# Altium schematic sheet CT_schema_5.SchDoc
size 297 x 173 mm
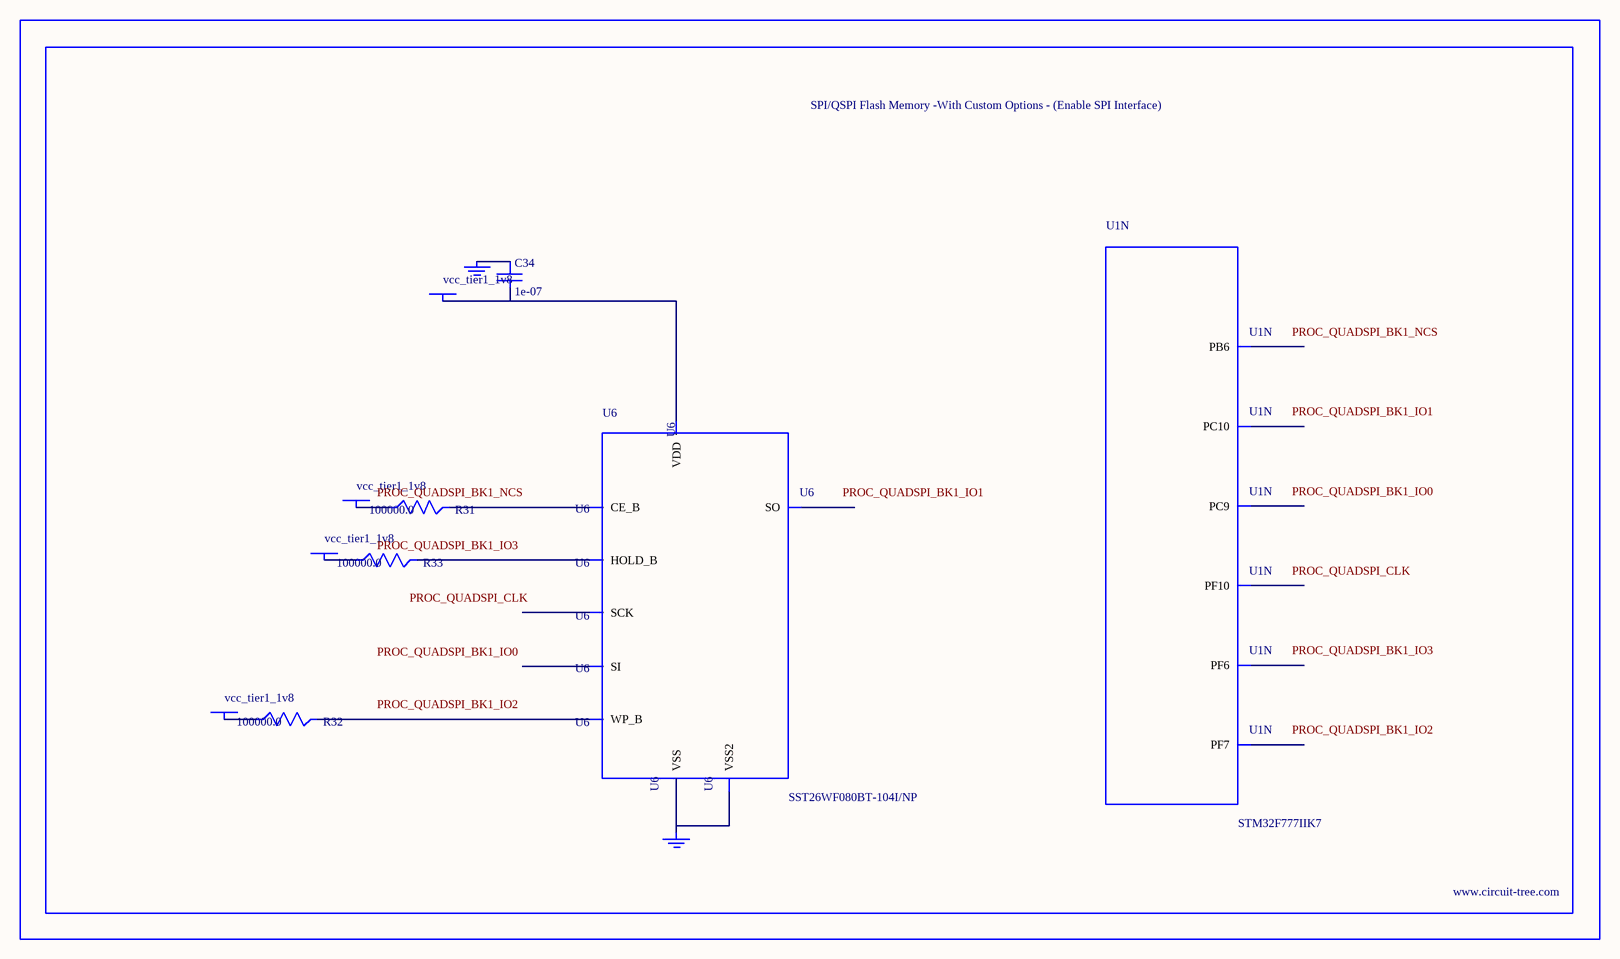
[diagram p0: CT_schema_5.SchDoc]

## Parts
BORDER4  (no value)
C34  1e-07  [C0402]
GND_INSTANCE_4_0  (no value)
GND_INSTANCE_4_1  (no value)
POWER_INSTANCE_4_0  vcc_tier1_1v8
POWER_INSTANCE_4_1  vcc_tier1_1v8
POWER_INSTANCE_4_2  vcc_tier1_1v8
POWER_INSTANCE_4_3  vcc_tier1_1v8
R31  100000.0  [R0603]
R32  100000.0  [R0603]
R33  100000.0  [R0603]
U1  STM32F777IIK7  [UFBGA176_25]  (part N of 15)
U6  SST26WF080BT-104I/NP  [USON-8]

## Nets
NetC34_1: C34.1 GND_INSTANCE_4_0.0(GND)
NetC34_2: C34.2 POWER_INSTANCE_4_3.0(PWR) U6.8(VDD)
NetGND_INSTANCE_4_1_0: GND_INSTANCE_4_1.0(GND) U6.4(VSS) U6.9(VSS2)
NetPOWER_INSTANCE_4_0_0: POWER_INSTANCE_4_0.0(PWR) R31.1
NetPOWER_INSTANCE_4_1_0: POWER_INSTANCE_4_1.0(PWR) R32.1
NetPOWER_INSTANCE_4_2_0: POWER_INSTANCE_4_2.0(PWR) R33.1
NetR31_2: R31.2 U6.1(CE_B)
NetR32_2: R32.2 U6.3(WP_B)
NetR33_2: R33.2 U6.7(HOLD_B)

Not connected (* = marked no-connect by the designer): U1 B6(PB6) B14(PC10) F14(PC9) K1(PF7) K2(PF6) L1(PF10); U6 2(SO) 5(SI) 6(SCK)

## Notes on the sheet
- Labels drawn without touching a wire or pin: PROC_QUADSPI_BK1_IO0, PROC_QUADSPI_BK1_IO1, PROC_QUADSPI_BK1_IO2, PROC_QUADSPI_BK1_IO3, PROC_QUADSPI_BK1_NCS, PROC_QUADSPI_CLK

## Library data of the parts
BORDER4 = BORDER_PAGE4
C34 = C0402C104K3RACTU
GND_INSTANCE_4_0 GND_INSTANCE_4_1 = GND
POWER_INSTANCE_4_0-POWER_INSTANCE_4_3 = PWR
R31-R33 = RC0603JR-07100KL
